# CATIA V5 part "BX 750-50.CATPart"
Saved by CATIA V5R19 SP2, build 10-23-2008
Part number: BX 750-50
Bounding box of the stored display mesh (mm): x -47.487 to 47.487, y -47.487 to 47.487, z 0 to 255
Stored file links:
  C:\Users\Bora\Desktop\3D Katı model\BX serisi\BX 750\BX 750-50.CATPart
  C:\Program Files\Dassault Systemes\B19\intel_a\reffiles\standard\MetricThickPitch.txt
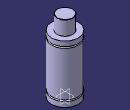
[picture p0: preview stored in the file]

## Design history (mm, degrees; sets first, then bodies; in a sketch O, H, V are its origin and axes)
Body1 (main body)
  Sketch1 on yz-plane, origin (0, 0, 0), H (0, 1, 0), V (0, 0, 1)
    point P1 (47.5, 18.5)
    point P3 (47.5, 181.5)
    point P4 (47.5, 23.5)
    point P5 (27.5, 254)
    point P7 (27.5, 254)
    point P10 (47.5, 186.5)
    point P11 (47.5, 23.5)
    point P12 (47.5, 18.5)
    point P13 (47.5, 186.5)
    point P14 (47.5, 181.5)
    line L1 (47.5, 18.5) -> (47.5, 0)
    line L2 (47.5, 181.5) -> (47.5, 23.5)
    arc A1 centre (26.5, 254) radius 1 from (27.5, 254) to (26.5, 255) ccw
    line L3 (27.5, 254) -> (27.5, 204)
    line L4 (47.5, 204) -> (47.5, 186.5)
    arc A2 centre (47.5, 21) radius 2.5 from (47.5, 23.5) to (47.5, 18.5) ccw
    arc A3 centre (47.5, 184) radius 2.5 from (47.5, 186.5) to (47.5, 181.5) ccw
    line L5 (26.5, 255) -> (0, 255)
    point P15 (0, 255)
    line L6 (27.5, 204) -> (47.5, 204)
    line L7 (47.5, 0) -> (0, 0)
    tangency: L5 A1
    coincidence: P15 V, P1 P12, P3 P14, P4 P11, P5 P7, P10 P13
    horizontal: L6 H, L7 H
  Shaft1: profile Sketch1, axis Sketch1.V, angle 360
  Sketch2 on face of Shaft1 from Sketch1.L7, origin (0, 0, 0), H (1, 0, 0), V (0, -1, 0)
    point P1 (25, 0)
    distance P1 V = 25
  Hole1: placed by Sketch2, at (25, 0, 0) direction (0, 0, 1), diameter 6.647, depth 10, threaded "M8", thread diameter 8, thread depth 10, pitch 1.25
  CircPattern1: of Hole1, instances 4, angular step 90, axis from xy-plane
